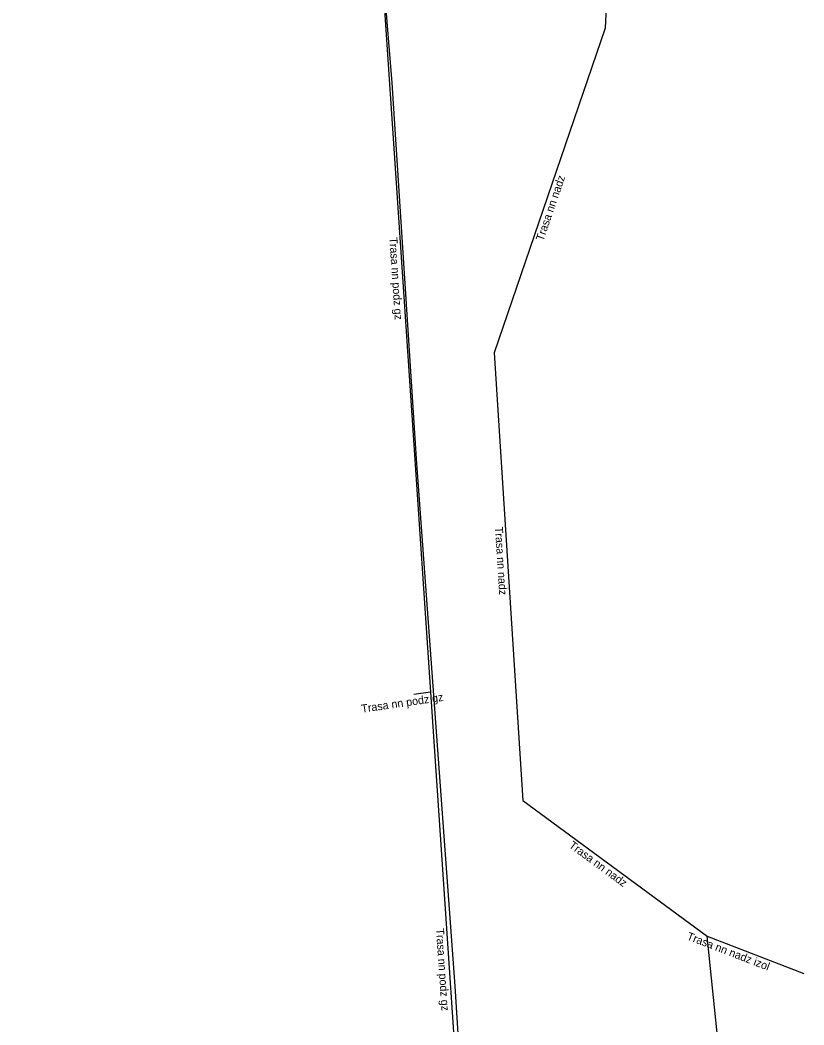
# Model space of a CAD drawing. Extents: x -725057 to -724754, y -1049160 to -1048651.
# Drawn here: x -724956.7 to -724907.8, y -1048993.6 to -1048930.9 of the extents above; entities that cross this region are included whole.
import ezdxf

# ---------------------------------------------------------------- set-up
doc = ezdxf.new("R2010")
doc.units = 0
for name, color, linetype in [('Popiskový text - Ostatní atributy Trasy', 7, 'Continuous'), ('Spojnice NN', 7, 'Continuous'), ('Spojnice VN', 7, 'Continuous')]:
    doc.layers.add(name, color=color, linetype=linetype)

msp = doc.modelspace()

# ---------------------------------------------------------------- linework, layer by layer
at = {"layer": 'Spojnice NN'}
for points in [[(-724918.48, -1048894.51), (-724920.199, -1048931.381)], [(-724934.42, -1048923.73), (-724931.11, -1048972.86)], [(-724920.199, -1048931.381), (-724927.13, -1048951.66)], [(-724927.13, -1048951.66), (-724925.34, -1048979.62)], [(-724931.11, -1048972.86), (-724932.14, -1048973.01)], [(-724931.11, -1048972.86), (-724928.59, -1049010.08)], [(-724925.34, -1048979.62), (-724913.828, -1048988.101)], [(-724909.957, -1049025.61), (-724913.828, -1048988.101)], [(-724913.828, -1048988.101), (-724907.796, -1048990.423)]]:
    msp.add_lwpolyline(points, dxfattribs=at)
at = {"layer": 'Spojnice VN'}
msp.add_lwpolyline([(-724948.38, -1048875.85), (-724953, -1048883.6), (-724956.06, -1048887.41), (-724956.72, -1048889.07), (-724956.05, -1048890.35), (-724937.04, -1048905.1), (-724935.78, -1048907.08), (-724933.51, -1048934.79), (-724931.99, -1048958.28), (-724929.58, -1048991.23), (-724928.45, -1049009.35), (-724927.82, -1049010.29), (-724922.87, -1049013.13), (-724922.05, -1049014.45), (-724920.15, -1049051.91), (-724918.93, -1049078.06), (-724917.41, -1049089.83), (-724917.12, -1049112.39), (-724916.32, -1049116.09), (-724915.71, -1049122.92), (-724916.11, -1049125.96), (-724915.65, -1049129.84)], dxfattribs=at)

# ---------------------------------------------------------------- texts
at = {"layer": 'Popiskový text - Ostatní atributy Trasy'}
for s, rotation, p in [('Trasa nn nadz', 71.13049, (-724924.067, -1048944.709)), ('Trasa nn podz gz', 273.85432, (-724933.675, -1048944.454)), ('Trasa nn nadz', 273.66308, (-724927.085, -1048962.541)), ('Trasa nn podz gz', 8.2858, (-724935.384, -1048974.14)), ('Trasa nn nadz', 323.62057, (-724922.503, -1048982.517)), ('Trasa nn podz gz', 273.87333, (-724930.761, -1048987.629)), ('Trasa nn nadz izol', 338.94594, (-724915.143, -1048988.291))]:
    msp.add_text(s, height=0.5, rotation=rotation, dxfattribs=at).set_placement(p)

doc.saveas('drawing.dxf')
